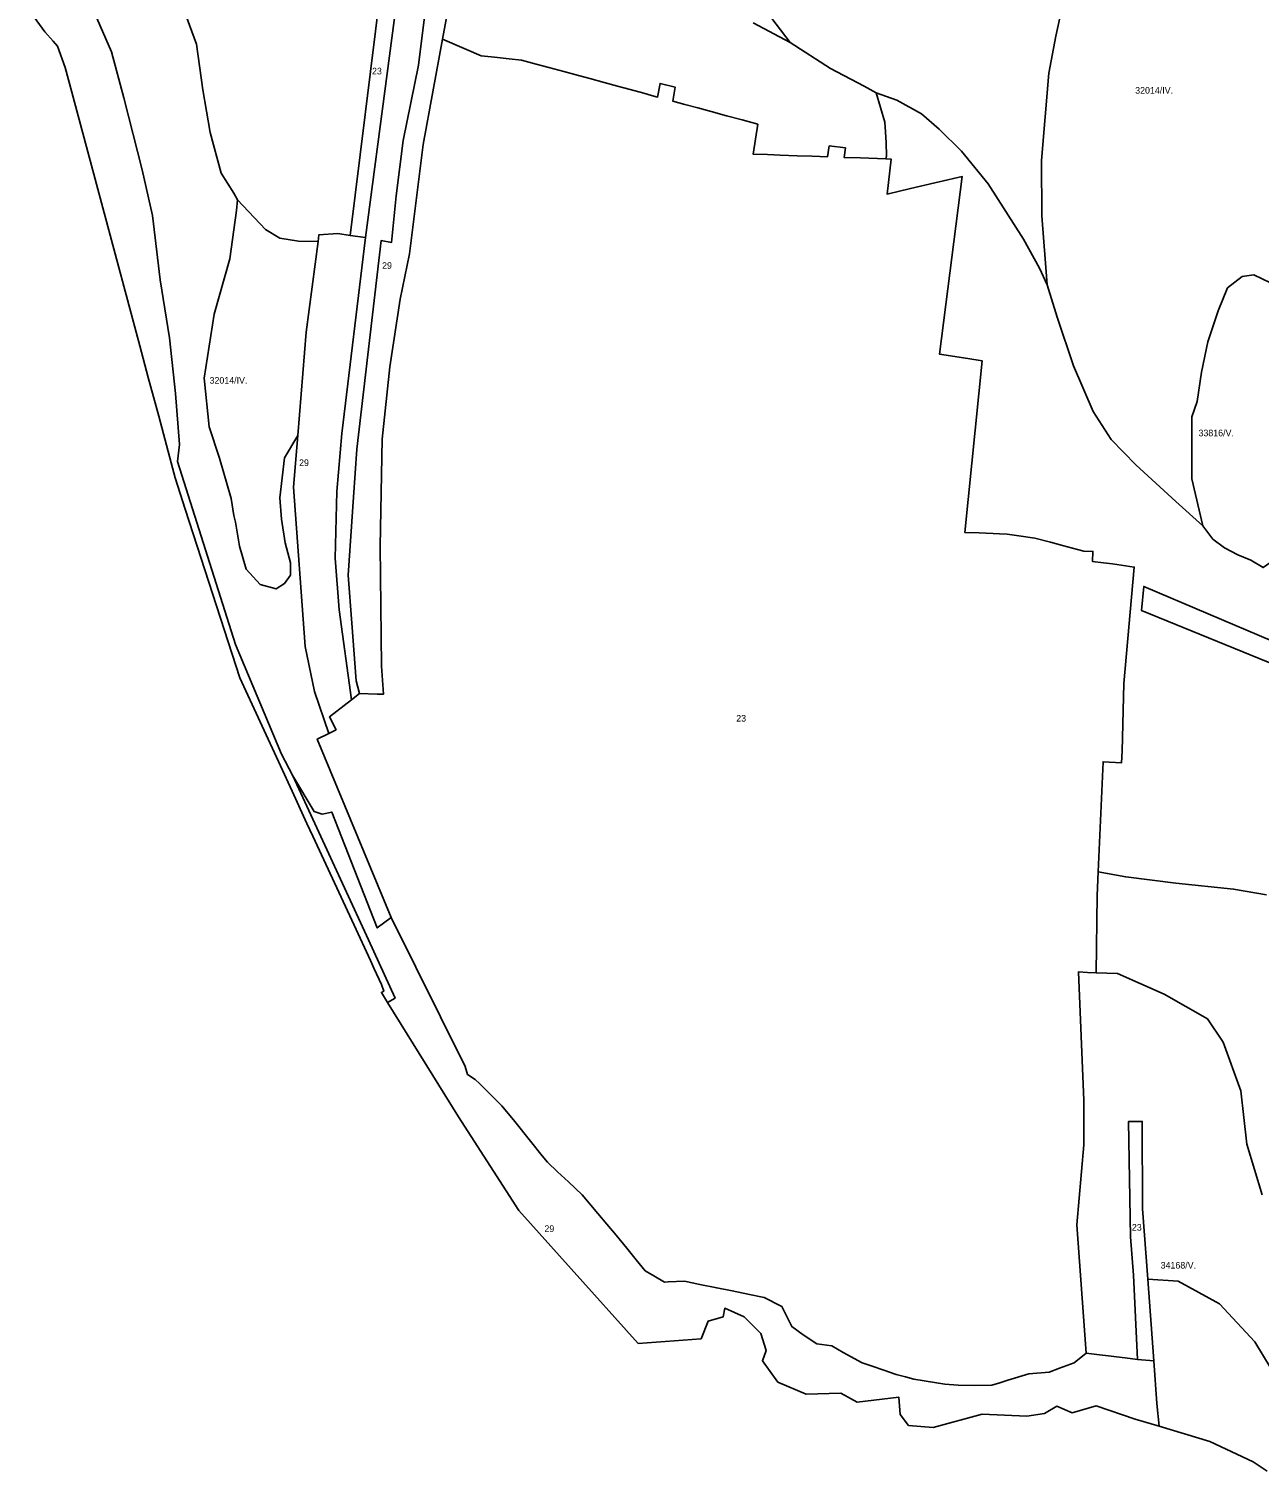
# Model space of a CAD drawing. Extents: x -521621 to -516761, y -1190184 to -1184927.
# Drawn here: x -520746 to -520002, y -1189839 to -1188967 of the extents above; entities that cross this region are included whole.
import ezdxf

# ---------------------------------------------------------------- set-up
doc = ezdxf.new("R2010")
doc.units = 0
doc.layers.add('BPEJ_s', color=7, linetype='Continuous')

msp = doc.modelspace()

# ---------------------------------------------------------------- linework, layer by layer
at = {"layer": 'BPEJ_s'}
for points in [[(-520477.32, -1188872.97), (-520495.91, -1188972.7), (-520507.62, -1189036.38), (-520515.9, -1189102.5), (-520521.61, -1189129.92), (-520527.8, -1189170.94), (-520532.37, -1189214.69), (-520533.68, -1189279.37), (-520532.86, -1189351.91), (-520531.55, -1189368.88), (-520535.46, -1189368.99), (-520546.19, -1189368.57), (-520548.15, -1189360.77), (-520550.82, -1189325.88), (-520553.03, -1189296.96), (-520549.82, -1189249.83), (-520547.84, -1189220.79), (-520533.05, -1189094.62), (-520526.75, -1189095.72), (-520523.91, -1189067.49), (-520519.66, -1189033.98), (-520510.37, -1188988.44), (-520504.7, -1188941.33)], [(-520308.08, -1188962.92), (-520285.71, -1188974.72), (-520261.31, -1188990.59), (-520240.98, -1189001.17), (-520233.66, -1189005.24), (-520228.4, -1189023.02), (-520228.01, -1189028.87), (-520227.61, -1189035.38), (-520227.47, -1189043.35), (-520227.76, -1189045.13), (-520243.06, -1189044.6), (-520253.03, -1189044.25), (-520252.21, -1189038.39), (-520261.97, -1189037.38), (-520262.98, -1189043.9), (-520272.43, -1189043.57), (-520281.52, -1189043.25), (-520291.62, -1189042.89), (-520299.46, -1189042.62), (-520308.02, -1189042.32), (-520305.25, -1189024.2), (-520314.76, -1189021.62), (-520324.15, -1189019.07), (-520333.37, -1189016.57), (-520341.46, -1189014.37), (-520349.31, -1189012.24), (-520356.69, -1189010.24), (-520355.2, -1189001.81), (-520364.33, -1188999.52), (-520365.8, -1189007.77), (-520369.48, -1189006.77), (-520374.18, -1189005.5), (-520382.41, -1189003.26), (-520390.18, -1189001.15), (-520398.17, -1188998.99), (-520406.87, -1188996.63), (-520413.72, -1188994.77), (-520422.53, -1188992.38), (-520431.54, -1188989.94), (-520439.34, -1188987.82), (-520448.19, -1188985.42), (-520455.58, -1188984.63), (-520464.4, -1188983.69), (-520472.59, -1188982.82), (-520481.48, -1188978.96), (-520495.91, -1188972.7), (-520477.32, -1188872.97)], [(-520504.7, -1188941.33), (-520510.37, -1188988.44), (-520519.66, -1189033.98), (-520523.91, -1189067.49), (-520526.75, -1189095.72), (-520533.05, -1189094.62), (-520547.84, -1189220.79), (-520549.82, -1189249.83), (-520553.03, -1189296.96), (-520550.82, -1189325.88), (-520548.15, -1189360.77), (-520546.19, -1189368.57), (-520550.9, -1189372.24), (-520558.39, -1189317.88), (-520560.76, -1189286.66), (-520559.81, -1189246.25), (-520556.81, -1189211.31), (-520542.47, -1189092.69), (-520516.33, -1188894.07)], [(-520711.81, -1188944.14), (-520696.18, -1188980.37), (-520688.6, -1189008.3), (-520677.62, -1189051.71), (-520671.33, -1189079.36), (-520666.68, -1189118.23), (-520661.04, -1189153.45), (-520657.38, -1189187), (-520655.06, -1189217.9), (-520656.3, -1189228.21), (-520621.19, -1189338.81), (-520593.34, -1189405.19), (-520586.42, -1189418.34), (-520540.64, -1189517.55), (-520524.58, -1189552.66), (-520529.21, -1189555.28), (-520532.93, -1189549.27), (-520531.4, -1189548.48), (-520532.86, -1189544.46), (-520537.19, -1189535.09), (-520539.55, -1189529.98), (-520549.44, -1189508.61), (-520574.32, -1189454.83), (-520577.92, -1189447.03), (-520586.89, -1189427.64), (-520594.01, -1189412.24), (-520618.61, -1189359.05), (-520644.28, -1189279.39), (-520651.5, -1189256.99), (-520657.57, -1189238.14), (-520660.05, -1189228.9), (-520667.59, -1189200.83), (-520673.89, -1189177.34), (-520679.02, -1189158.24), (-520701.41, -1189074.84), (-520706.08, -1189057.43), (-520719.4, -1189007.82), (-520720.18, -1189004.9), (-520724.21, -1188989.9), (-520728.7, -1188977.01), (-520731.45, -1188973.94), (-520736.45, -1188968.35), (-520746.13, -1188954.96)], [(-520654.01, -1188950.6), (-520644.67, -1188975.88), (-520640.83, -1189003.35), (-520636.43, -1189029.18), (-520629.84, -1189053.9), (-520622.16, -1189065.99), (-520619.96, -1189069.84), (-520620.53, -1189076.37), (-520624.51, -1189105.6), (-520634.14, -1189139.16), (-520640.12, -1189177.7), (-520637.13, -1189207.27), (-520630.82, -1189226.21), (-520623.85, -1189250.46), (-520622.19, -1189260.76), (-520621.12, -1189264.96), (-520618.8, -1189279.32), (-520614.64, -1189293.21), (-520606.3, -1189302.48), (-520596.58, -1189305.26), (-520591.49, -1189302.01), (-520587.79, -1189296.92), (-520587.79, -1189289.51), (-520591.03, -1189277.46), (-520593.34, -1189263.1), (-520594.27, -1189250.14), (-520591.49, -1189226.05), (-520583.52, -1189212.38), (-520586.1, -1189243.76), (-520579.01, -1189340.15), (-520573.34, -1189367.35), (-520564.67, -1189392.59), (-520571.69, -1189396.1), (-520527.07, -1189503.87), (-520535.45, -1189510.25), (-520562.89, -1189440.16), (-520568.68, -1189441.45), (-520573.61, -1189439.94), (-520586.42, -1189418.34), (-520593.34, -1189405.19), (-520621.19, -1189338.81), (-520656.3, -1189228.21), (-520655.06, -1189217.9), (-520657.38, -1189187), (-520661.04, -1189153.45), (-520666.68, -1189118.23), (-520671.33, -1189079.36), (-520677.62, -1189051.71), (-520688.6, -1189008.3), (-520696.18, -1188980.37), (-520711.81, -1188944.14)], [(-520533.51, -1188943.43), (-520551.79, -1189091.48), (-520559.19, -1189090.38), (-520570.7, -1189091.01), (-520571.23, -1189095.13), (-520583.11, -1189094.86), (-520594.24, -1189093.13), (-520602.94, -1189087.97), (-520619.96, -1189069.84), (-520622.16, -1189065.99), (-520629.84, -1189053.9), (-520636.43, -1189029.18), (-520640.83, -1189003.35), (-520644.67, -1188975.88), (-520654.01, -1188950.6)], [(-520119.74, -1188946.84), (-520125.03, -1188971.03), (-520129.2, -1188993.32), (-520133.72, -1189046.21), (-520133.45, -1189079.7), (-520130.27, -1189121.42), (-520134.78, -1189111.32), (-520144.48, -1189093.72), (-520165.86, -1189060.36), (-520182.06, -1189040.56), (-520195.6, -1189027.28), (-520206.23, -1189017.84), (-520221.1, -1189009.74), (-520233.66, -1189005.24), (-520240.98, -1189001.17), (-520261.31, -1188990.59), (-520285.71, -1188974.72), (-520299.94, -1188956)], [(-519995.11, -1189120.08), (-520005.14, -1189115.37), (-520012.36, -1189116.31), (-520021.14, -1189123.22), (-520026.79, -1189137.03), (-520033.06, -1189155.86), (-520036.82, -1189174.06), (-520039.43, -1189191.85), (-520042.62, -1189201.15), (-520042.62, -1189238.63), (-520035.98, -1189267.06), (-520052.45, -1189252.45), (-520076.61, -1189230.12), (-520091.49, -1189214.97), (-520102.38, -1189197.97), (-520114.33, -1189170.32), (-520124.16, -1189140.82), (-520130.27, -1189121.42), (-520133.45, -1189079.7), (-520133.72, -1189046.21), (-520129.2, -1188993.32), (-520125.03, -1188971.03), (-520119.74, -1188946.84)], [(-520299.94, -1188956), (-520285.71, -1188974.72), (-520308.08, -1188962.92)], [(-519997.55, -1189490.16), (-520017.45, -1189486.79), (-520052.46, -1189483.23), (-520082.72, -1189479.37), (-520099.33, -1189476.24), (-520096.38, -1189409.78), (-520085.18, -1189410.41), (-520084.88, -1189403.44), (-520083.91, -1189362.4), (-520077.54, -1189292.05), (-520090.61, -1189290.12), (-520096.09, -1189289.38), (-520102.83, -1189288.62), (-520102.5, -1189282.58), (-520107.94, -1189282.39), (-520111.84, -1189281.36), (-520120.86, -1189278.98), (-520128.2, -1189277.05), (-520137.57, -1189274.58), (-520145.93, -1189273.33), (-520154.45, -1189272.06), (-520158.99, -1189271.85), (-520162.88, -1189271.7), (-520171.35, -1189271.37), (-520179.92, -1189271.03), (-520169.48, -1189167.35), (-520178.16, -1189165.99), (-520195.41, -1189163.27), (-520181.56, -1189055.85), (-520209.49, -1189062.37), (-520218.76, -1189064.54), (-520227.02, -1189066.47), (-520224.58, -1189045.25), (-520227.76, -1189045.13), (-520227.47, -1189043.35), (-520227.61, -1189035.38), (-520228.01, -1189028.87), (-520228.4, -1189023.02), (-520233.66, -1189005.24), (-520221.1, -1189009.74), (-520206.23, -1189017.84), (-520195.6, -1189027.28), (-520182.06, -1189040.56), (-520165.86, -1189060.36), (-520144.48, -1189093.72), (-520134.78, -1189111.32), (-520130.27, -1189121.42), (-520124.16, -1189140.82), (-520114.33, -1189170.32), (-520102.38, -1189197.97), (-520091.49, -1189214.97), (-520076.61, -1189230.12), (-520052.45, -1189252.45), (-520035.98, -1189267.06), (-520029.93, -1189275.14), (-520022.89, -1189280.37), (-520014.94, -1189284.68), (-520006.99, -1189287.86), (-519999.5, -1189292.36)], [(-519948.89, -1189368.76), (-520002.08, -1189347.37), (-520073.06, -1189318.39), (-520071.75, -1189303.77), (-519993.99, -1189336.93)], [(-519993.99, -1189336.93), (-520071.75, -1189303.77), (-520073.06, -1189318.39), (-520002.08, -1189347.37), (-519948.89, -1189368.76)], [(-520000.25, -1189671.74), (-520009.4, -1189641.12), (-520013.12, -1189608.77), (-520023.73, -1189579.27), (-520033.18, -1189565.25), (-520059.38, -1189550.31), (-520087.71, -1189537.81), (-520100.52, -1189537.37), (-520099.97, -1189490.62), (-520099.33, -1189476.24), (-520082.72, -1189479.37), (-520052.46, -1189483.23), (-520017.45, -1189486.79), (-519997.55, -1189490.16)], [(-519994.76, -1189776.95), (-520004.52, -1189760.61), (-520025.92, -1189737.57), (-520050.88, -1189723.95), (-520069.34, -1189722.63), (-520072.48, -1189680.11), (-520072.74, -1189627.32), (-520080.93, -1189627.31), (-520079.78, -1189697.16), (-520077.96, -1189720.29), (-520075.61, -1189771.21), (-520083.08, -1189770.3), (-520088.26, -1189769.68), (-520093.08, -1189769.09), (-520098.64, -1189768.42), (-520106.69, -1189767.45), (-520112.34, -1189689.89), (-520108.13, -1189641.35), (-520108.13, -1189614.58), (-520111.28, -1189536.86), (-520105.83, -1189537.23), (-520100.52, -1189537.37), (-520087.71, -1189537.81), (-520059.38, -1189550.31), (-520033.18, -1189565.25), (-520023.73, -1189579.27), (-520013.12, -1189608.77), (-520009.4, -1189641.12), (-520000.25, -1189671.74)], [(-519997.21, -1189838.78), (-520005.61, -1189833.21), (-520031.82, -1189820.91), (-520062.53, -1189811.54), (-520063.79, -1189797.96), (-520065.69, -1189771.99), (-520069.34, -1189722.63), (-520050.88, -1189723.95), (-520025.92, -1189737.57), (-520004.52, -1189760.61), (-519994.76, -1189776.95)]]:
    msp.add_lwpolyline(points, dxfattribs=at)
for points in [[(-520551.79, -1189091.48), (-520533.51, -1188943.43), (-520524.53, -1188892.81), (-520516.33, -1188894.07), (-520542.47, -1189092.69)], [(-520564.67, -1189392.59), (-520560.28, -1189390.39), (-520564.31, -1189382.67), (-520550.9, -1189372.24), (-520546.19, -1189368.57), (-520535.46, -1189368.99), (-520531.55, -1189368.88), (-520532.86, -1189351.91), (-520533.68, -1189279.37), (-520532.37, -1189214.69), (-520527.8, -1189170.94), (-520521.61, -1189129.92), (-520515.9, -1189102.5), (-520507.62, -1189036.38), (-520495.91, -1188972.7), (-520481.48, -1188978.96), (-520472.59, -1188982.82), (-520464.4, -1188983.69), (-520455.58, -1188984.63), (-520448.19, -1188985.42), (-520439.34, -1188987.82), (-520431.54, -1188989.94), (-520422.53, -1188992.38), (-520413.72, -1188994.77), (-520406.87, -1188996.63), (-520398.17, -1188998.99), (-520390.18, -1189001.15), (-520382.41, -1189003.26), (-520374.18, -1189005.5), (-520369.48, -1189006.77), (-520365.8, -1189007.77), (-520364.33, -1188999.52), (-520355.2, -1189001.81), (-520356.69, -1189010.24), (-520349.31, -1189012.24), (-520341.46, -1189014.37), (-520333.37, -1189016.57), (-520324.15, -1189019.07), (-520314.76, -1189021.62), (-520305.25, -1189024.2), (-520308.02, -1189042.32), (-520299.46, -1189042.62), (-520291.62, -1189042.89), (-520281.52, -1189043.25), (-520272.43, -1189043.57), (-520262.98, -1189043.9), (-520261.97, -1189037.38), (-520252.21, -1189038.39), (-520253.03, -1189044.25), (-520243.06, -1189044.6), (-520227.76, -1189045.13), (-520224.58, -1189045.25), (-520227.02, -1189066.47), (-520218.76, -1189064.54), (-520209.49, -1189062.37), (-520181.56, -1189055.85), (-520195.41, -1189163.27), (-520178.16, -1189165.99), (-520169.48, -1189167.35), (-520179.92, -1189271.03), (-520171.35, -1189271.37), (-520162.88, -1189271.7), (-520158.99, -1189271.85), (-520154.45, -1189272.06), (-520145.93, -1189273.33), (-520137.57, -1189274.58), (-520128.2, -1189277.05), (-520120.86, -1189278.98), (-520111.84, -1189281.36), (-520107.94, -1189282.39), (-520102.5, -1189282.58), (-520102.83, -1189288.62), (-520096.09, -1189289.38), (-520090.61, -1189290.12), (-520077.54, -1189292.05), (-520083.91, -1189362.4), (-520084.88, -1189403.44), (-520085.18, -1189410.41), (-520096.38, -1189409.78), (-520099.33, -1189476.24), (-520099.97, -1189490.62), (-520100.52, -1189537.37), (-520105.83, -1189537.23), (-520111.28, -1189536.86), (-520108.13, -1189614.58), (-520108.13, -1189641.35), (-520112.34, -1189689.89), (-520106.69, -1189767.45), (-520113.85, -1189773.18), (-520122.69, -1189776.52), (-520129.03, -1189778.85), (-520141.36, -1189779.84), (-520153.97, -1189783.8), (-520158.9, -1189785.37), (-520163.62, -1189786.87), (-520174.28, -1189786.88), (-520184.08, -1189786.86), (-520192.2, -1189786.08), (-520210.86, -1189783.15), (-520215.98, -1189781.79), (-520221.57, -1189780.31), (-520229.06, -1189777.73), (-520236.09, -1189775.31), (-520242.02, -1189773.27), (-520253.51, -1189767.07), (-520260.39, -1189763.01), (-520269.52, -1189761.7), (-520277.69, -1189756.26), (-520284.62, -1189751.33), (-520290.69, -1189739.15), (-520301.48, -1189733.72), (-520310.19, -1189731.96), (-520320.67, -1189729.83), (-520330.09, -1189727.93), (-520340.25, -1189725.87), (-520349.66, -1189723.96), (-520359.41, -1189724.36), (-520361.57, -1189724.45), (-520368.13, -1189720.69), (-520373.33, -1189717.7), (-520378.84, -1189711.05), (-520384.47, -1189703.9), (-520390.87, -1189696.02), (-520396.56, -1189689.33), (-520401.98, -1189682.96), (-520411.55, -1189671.72), (-520419.77, -1189663.89), (-520426.31, -1189657.72), (-520432.47, -1189651.89), (-520435.59, -1189648.02), (-520442.69, -1189639.2), (-520452.26, -1189627.31), (-520459.96, -1189617.75), (-520470.04, -1189607.81), (-520473.57, -1189604.34), (-520476.11, -1189601.86), (-520480.91, -1189598.89), (-520482.14, -1189594.07), (-520527.07, -1189503.87), (-520571.69, -1189396.1)], [(-520619.96, -1189069.84), (-520602.94, -1189087.97), (-520594.24, -1189093.13), (-520583.11, -1189094.86), (-520571.23, -1189095.13), (-520578.39, -1189149.88), (-520583.52, -1189212.38), (-520591.49, -1189226.05), (-520594.27, -1189250.14), (-520593.34, -1189263.1), (-520591.03, -1189277.46), (-520587.79, -1189289.51), (-520587.79, -1189296.92), (-520591.49, -1189302.01), (-520596.58, -1189305.26), (-520606.3, -1189302.48), (-520614.64, -1189293.21), (-520618.8, -1189279.32), (-520621.12, -1189264.96), (-520622.19, -1189260.76), (-520623.85, -1189250.46), (-520630.82, -1189226.21), (-520637.13, -1189207.27), (-520640.12, -1189177.7), (-520634.14, -1189139.16), (-520624.51, -1189105.6), (-520620.53, -1189076.37)], [(-520583.52, -1189212.38), (-520578.39, -1189149.88), (-520571.23, -1189095.13), (-520570.7, -1189091.01), (-520559.19, -1189090.38), (-520551.79, -1189091.48), (-520542.47, -1189092.69), (-520556.81, -1189211.31), (-520559.81, -1189246.25), (-520560.76, -1189286.66), (-520558.39, -1189317.88), (-520550.9, -1189372.24), (-520564.31, -1189382.67), (-520560.28, -1189390.39), (-520564.67, -1189392.59), (-520573.34, -1189367.35), (-520579.01, -1189340.15), (-520586.1, -1189243.76)], [(-520035.98, -1189267.06), (-520042.62, -1189238.63), (-520042.62, -1189201.15), (-520039.43, -1189191.85), (-520036.82, -1189174.06), (-520033.06, -1189155.86), (-520026.79, -1189137.03), (-520021.14, -1189123.22), (-520012.36, -1189116.31), (-520005.14, -1189115.37), (-519995.11, -1189120.08), (-519991.34, -1189129.81), (-519985.7, -1189150.52), (-519980.5, -1189169.48), (-519973.72, -1189202.75), (-519973.72, -1189233.3), (-519979.83, -1189267.24), (-519990, -1189285.57), (-519999.5, -1189292.36), (-520006.99, -1189287.86), (-520014.94, -1189284.68), (-520022.89, -1189280.37), (-520029.93, -1189275.14)], [(-520586.42, -1189418.34), (-520573.61, -1189439.94), (-520568.68, -1189441.45), (-520562.89, -1189440.16), (-520535.45, -1189510.25), (-520527.07, -1189503.87), (-520482.14, -1189594.07), (-520480.91, -1189598.89), (-520476.11, -1189601.86), (-520473.57, -1189604.34), (-520470.04, -1189607.81), (-520459.96, -1189617.75), (-520452.26, -1189627.31), (-520442.69, -1189639.2), (-520435.59, -1189648.02), (-520432.47, -1189651.89), (-520426.31, -1189657.72), (-520419.77, -1189663.89), (-520411.55, -1189671.72), (-520401.98, -1189682.96), (-520396.56, -1189689.33), (-520390.87, -1189696.02), (-520384.47, -1189703.9), (-520378.84, -1189711.05), (-520373.33, -1189717.7), (-520368.13, -1189720.69), (-520361.57, -1189724.45), (-520359.41, -1189724.36), (-520349.66, -1189723.96), (-520340.25, -1189725.87), (-520330.09, -1189727.93), (-520320.67, -1189729.83), (-520310.19, -1189731.96), (-520301.48, -1189733.72), (-520290.69, -1189739.15), (-520284.62, -1189751.33), (-520277.69, -1189756.26), (-520269.52, -1189761.7), (-520260.39, -1189763.01), (-520253.51, -1189767.07), (-520242.02, -1189773.27), (-520236.09, -1189775.31), (-520229.06, -1189777.73), (-520221.57, -1189780.31), (-520215.98, -1189781.79), (-520210.86, -1189783.15), (-520192.2, -1189786.08), (-520184.08, -1189786.86), (-520174.28, -1189786.88), (-520163.62, -1189786.87), (-520158.9, -1189785.37), (-520153.97, -1189783.8), (-520141.36, -1189779.84), (-520129.03, -1189778.85), (-520122.69, -1189776.52), (-520113.85, -1189773.18), (-520106.69, -1189767.45), (-520098.64, -1189768.42), (-520093.08, -1189769.09), (-520088.26, -1189769.68), (-520083.08, -1189770.3), (-520075.61, -1189771.21), (-520065.69, -1189771.99), (-520063.79, -1189797.96), (-520062.53, -1189811.54), (-520077, -1189807.39), (-520100.52, -1189799.21), (-520115.13, -1189803.59), (-520124.27, -1189799.49), (-520131.78, -1189804), (-520142.56, -1189805.5), (-520169.45, -1189804.4), (-520199.25, -1189812.46), (-520214, -1189811.1), (-520219.18, -1189804.54), (-520220, -1189794.03), (-520245.12, -1189797.04), (-520255.08, -1189791.71), (-520275.97, -1189792.26), (-520293.04, -1189784.88), (-520302.41, -1189772.13), (-520300.11, -1189765.76), (-520303.48, -1189755.49), (-520313.38, -1189745.39), (-520325.24, -1189740.26), (-520326.12, -1189745.39), (-520335.32, -1189748.05), (-520339.57, -1189758.68), (-520377.61, -1189761.51), (-520418.13, -1189716.36), (-520449.7, -1189681.23), (-520486.32, -1189624.56), (-520529.21, -1189555.28), (-520524.58, -1189552.66), (-520540.64, -1189517.55)], [(-520075.61, -1189771.21), (-520077.96, -1189720.29), (-520079.78, -1189697.16), (-520080.93, -1189627.31), (-520072.74, -1189627.32), (-520072.48, -1189680.11), (-520069.34, -1189722.63), (-520065.69, -1189771.99)]]:
    msp.add_lwpolyline(points, close=True, dxfattribs=at)

# ---------------------------------------------------------------- texts
for s, p in [('23', (-520538.58, -1188994.09)), ('32014/IV.', (-520076.96, -1189005.73)), ('29', (-520532.48, -1189111.66)), ('32014/IV.', (-520636.83, -1189181.1)), ('33816/V.', (-520038.68, -1189212.92)), ('29', (-520582.68, -1189230.93)), ('23', (-520318.26, -1189385.45)), ('29', (-520434.29, -1189694.11)), ('23', (-520078.96, -1189693.32)), ('34168/V.', (-520061.57, -1189716.25))]:
    msp.add_text(s, height=4, dxfattribs=at).set_placement(p)

doc.saveas('drawing.dxf')
